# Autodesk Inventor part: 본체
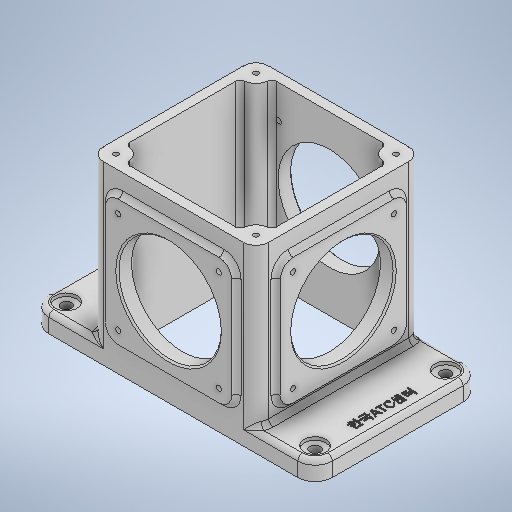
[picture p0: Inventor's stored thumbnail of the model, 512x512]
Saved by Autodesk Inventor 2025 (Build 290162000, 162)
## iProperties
Created: 2024-08
Part Number: 본체
Material: 알루미늄 6061
Document SubType Name: Modeling
Designer: rese9
Density: 2.7 g/cm^3
Appearance: 알루미늄 - 평지
Mass: 969.416 g
Surface Area: 957.183 cm^2
Volume: 359.043 cm^3
Sending System: Autodesk Inventor 2025
Preprocessor: ST-DEVELOPER v20
Author: jhkim
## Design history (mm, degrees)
feature "솔리드1"
node "솔리드2"
